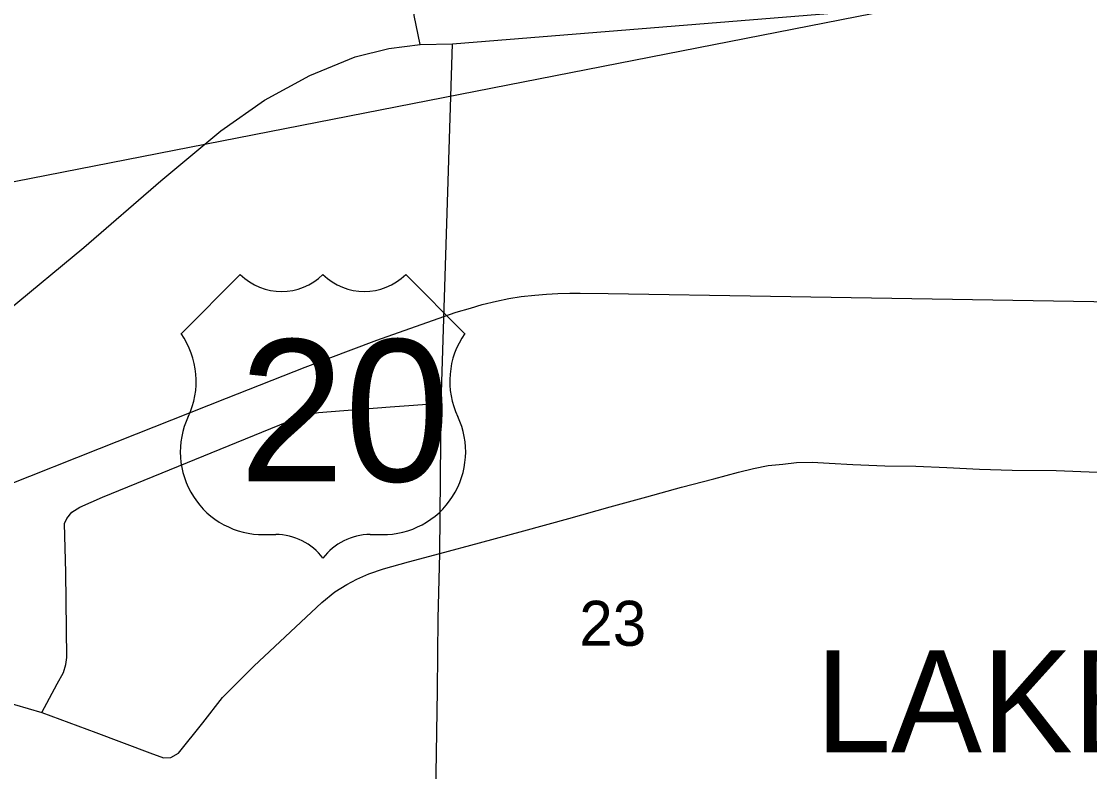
# Model space of a CAD drawing. Extents: x 2010165 to 2382125, y 1060529 to 1407316.
# Drawn here: x 2152111 to 2157356, y 1268955 to 1272638 of the extents above; entities that cross this region are included whole.
import ezdxf

# ---------------------------------------------------------------- set-up
doc = ezdxf.new("R2010")
doc.units = 0
for name, color, linetype in [('GM_X_City_Street', 7, 'Continuous'), ('GM_X_Corporation_Text', 7, 'Continuous'), ('GM_X_Rail_Line', 7, 'Continuous'), ('GM_X_Section', 7, 'Continuous'), ('GM_X_Section_Text', 7, 'Continuous'), ('GM_X_State_Route', 7, 'Continuous'), ('GM_X_US_Location', 7, 'Continuous'), ('GM_X_US_Route', 7, 'Continuous'), ('GM_X_US_Shield', 7, 'Continuous')]:
    doc.layers.add(name, color=color, linetype=linetype)

msp = doc.modelspace()

# ---------------------------------------------------------------- linework, layer by layer
at = {"layer": 'GM_X_City_Street'}
msp.add_lwpolyline([(2154068.8, 1272524), (2154039.3, 1272666.5), (2154045.6, 1272726.6), (2154080.3, 1272868.7), (2154111.6, 1272934.6)], dxfattribs=at)
at = {"layer": 'GM_X_Rail_Line'}
msp.add_lwpolyline([(2152040.8, 1270362), (2152495.3, 1270541), (2153117.6, 1270787.9), (2153503.8, 1270940.3), (2153856.2, 1271072.9), (2154157.1, 1271180), (2154246, 1271210.2), (2154315.5, 1271231.2), (2154373.8, 1271248.3), (2154444.4, 1271265.4), (2154504.8, 1271277.3), (2154565.1, 1271287.2), (2154631.8, 1271294.7), (2154689.3, 1271299.9), (2154745.7, 1271302.7), (2154803.6, 1271303.9), (2154854, 1271303.5), (2154992.2, 1271302.3), (2155789.9, 1271289.6), (2158369, 1271247.1)], dxfattribs=at)
at = {"layer": 'GM_X_Section'}
msp.add_lwpolyline([(2151655.6, 1267516.1), (2151689.6, 1271777.5), (2157458.5, 1272907.1), (2157439.6, 1267444.9)], close=True, dxfattribs=at)
at = {"layer": 'GM_X_State_Route'}
msp.add_lwpolyline([(2154152.1, 1268646.3), (2154140.4, 1268650.6), (2154147.4, 1268945.3), (2154154.1, 1269354.2), (2154156.9, 1269706.9), (2154165.9, 1270025.6), (2154172.9, 1270763.4)], dxfattribs=at)
at = {"layer": 'GM_X_US_Route'}
for points in [[(2154228.1, 1272528.1), (2157164, 1272766.7), (2158463.4, 1272870.5), (2160596.6, 1272854.8), (2161236.2, 1272830.9), (2163215.4, 1272696.6), (2163422.8, 1272682.1), (2165036.4, 1272542.8), (2165183.6, 1272513.4), (2165382.2, 1272454.5), (2168973.9, 1271364.2)], [(2152046.6, 1271221.4), (2152417.1, 1271528.4), (2152796.4, 1271855.5), (2153089.7, 1272101.7), (2153304.8, 1272251.1), (2153527.3, 1272372.5), (2153749.8, 1272463.5), (2153915, 1272505.7), (2154068.8, 1272524), (2154228.1, 1272528.1)], [(2154172.9, 1270763.4), (2154228.1, 1272528.1)], [(2152286.8, 1269386.3), (2152317.2, 1269442.8), (2152329.4, 1269481.7), (2152334.6, 1269514.9), (2152328.4, 1269932.7), (2152322.4, 1270173.6), (2152333.4, 1270198.5), (2152358.3, 1270229.4), (2152397.2, 1270253.4), (2152509.8, 1270303.2), (2153460.3, 1270690.4), (2153514.4, 1270708.7), (2153570.4, 1270718.9), (2153921, 1270746.2), (2154172.9, 1270763.4)], [(2152741, 1269048.4), (2152809.2, 1269023.1), (2152844.6, 1269025.3), (2152882.5, 1269045.5), (2153001.8, 1269194.7), (2153098.2, 1269319.9), (2153252.3, 1269472.9), (2153585.6, 1269785), (2153649.5, 1269837.3), (2153709.5, 1269873.6), (2153757.5, 1269899.9), (2153817.5, 1269926.1), (2153889.6, 1269950.4), (2154011.7, 1269985), (2154165.9, 1270025.6), (2154360.1, 1270078.4), (2154578.3, 1270137.4), (2154798.5, 1270198.3), (2155002.7, 1270255.1), (2155182.9, 1270303.9), (2155353.1, 1270352.6), (2155511.3, 1270393.3), (2155631.4, 1270425.8), (2155705.5, 1270444.1), (2155777.5, 1270458.4), (2155849.7, 1270464.7), (2155917.8, 1270473), (2155993.9, 1270475.2), (2156078.1, 1270469.5), (2156194.3, 1270463.9), (2156350.6, 1270456.5), (2156503, 1270455), (2156655.3, 1270447.6), (2156815.6, 1270440.1), (2156975.9, 1270434.7), (2157192.3, 1270433.5), (2157394.7, 1270426.2)], [(2152210.9, 1269245.2), (2152286.8, 1269386.3)], [(2151659.9, 1269363.2), (2151719.7, 1269358.6), (2152009.3, 1269303.9), (2152210.9, 1269245.2)], [(2152210.9, 1269245.2), (2152475.9, 1269146.8)], [(2152475.9, 1269146.8), (2152741, 1269048.4)]]:
    msp.add_lwpolyline(points, dxfattribs=at)
at = {"layer": 'GM_X_US_Shield'}
for p, q in [((2153185.8, 1271395.4), (2152895.8, 1271105.3)), ((2154288, 1271105.3), (2153997.9, 1271395.4)), ((2153301.8, 1270119.2), (2153359.8, 1270119.2)), ((2153823.9, 1270119.2), (2153881.9, 1270119.2))]:
    msp.add_line(p, q, dxfattribs=at)
for centre, radius, start, end in [((2153388.8, 1271602.5), 290, 225.573, 314.427), ((2153794.9, 1271602.5), 290, 225.573, 314.427), ((2152563.2, 1270872.4), 406.1, 334.5471, 35.0009), ((2154620.6, 1270872.4), 406.1, 144.9991, 205.4529), ((2153297.3, 1270525.2), 406.1, 154.8319, 270.6383), ((2153886.4, 1270525.2), 406.1, 269.3617, 25.1681), ((2153359.8, 1269829.2), 290, 36.8699, 90), ((2153823.9, 1269829.2), 290, 90, 143.1301)]:
    msp.add_arc(centre, radius, start, end, dxfattribs=at)

# ---------------------------------------------------------------- texts
at = {"layer": 'GM_X_Corporation_Text'}
msp.add_text('LAKEWOOD', height=500, rotation=0, dxfattribs=at).set_placement((2156009.7, 1269050.6))
at = {"layer": 'GM_X_Section_Text'}
msp.add_text('23', height=221, rotation=0, dxfattribs=at).set_placement((2154850.3, 1269573))
at = {"layer": 'GM_X_US_Location'}
for s in ['/', '0']:
    msp.add_text(s, height=1, dxfattribs=at).set_placement((2153591.5, 1270722.8))
msp.add_text('20', height=1, rotation=0, dxfattribs=at).set_placement((2153385.1, 1270515.8))
at = {"layer": 'GM_X_US_Shield'}
msp.add_text('20', height=696.1, dxfattribs=at).set_placement((2153180.3, 1270380.2))

doc.saveas('drawing.dxf')
